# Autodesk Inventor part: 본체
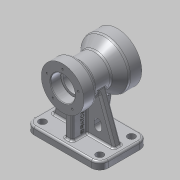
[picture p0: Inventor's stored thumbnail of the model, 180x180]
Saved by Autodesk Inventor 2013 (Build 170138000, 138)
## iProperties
Created: 2015-08
Part Number: 본체
Material: 알루미늄 6061
Document SubType Name: Modeling
Designer: ST1
Density: 2.71 g/cm^3
Mass: 1063.17 g
Surface Area: 754.745 cm^2
Volume: 392.315 cm^3
Author: ST1
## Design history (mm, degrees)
sketch "스케치1"
  geometry: L1 (-61, 40)-(61, 40); L2 (61, 40)-(61, -40); L3 (61, -40)-(-61, -40); L4 (-61, -40)-(-61, 40); 1 further point
  constraints: 8 end point, 2 parallel, 1 horizontal, 1 perpendicular
  dimensions: "d0" = 122 distance of L1.start L1.end; "d2" = 80 distance of L3.end L1.start; "d3" = 40 distance from line of point (0, 0) L1; "d4" = 61 distance from line of point (0, 0) L4
extrude "돌출1" new body sketch "스케치1" distance "d5" = 12; taper "d6" = 0 deg
sketch "스케치2"
  geometry: L1 (-40, 90)-(42.312, 90); L2 (-40, 110)-(-40, 125); L3 (-40, 125)-(-20, 125); L4 (-20, 125)-(-14.804, 116); L5 (-14.804, 116)-(13.315, 116); L6 (13.315, 116)-(30, 130); L7 (30, 130)-(50, 130); L8 (50, 130)-(50, 116); L9 (50, 116)-(30, 116); L10 (-40, 0)-(-40, 12) reference; L11 (30, 116)-(30, 109); L12 (30, 109)-(27, 109); L13 (27, 109)-(27, 106); L14 (27, 106)-(-23, 106); L15 (-23, 106)-(-23, 110); L16 (-23, 110)-(-40, 110); 1 further point
  constraints: 30 end point, 7 perpendicular, 5 parallel, 1 horizontal
  dimensions: "d7" = 90 distance from line of point (0, 0) L1; "d12" = 20 distance from line of L3.end L2; "d13" = 0 distance from line of L10 L1.start; "d14" = 0 distance from line of L1.start L2; "d15" = 90 distance between parallel lines of L8 L2; "d16" = 20 distance from line of L6.end L8; "d18" = 60 deg angle of L4 L5; "d60" = 80 diameter of L7 L1; "d61" = 70 diameter of L3 L1; "d62" = 52 diameter of L9 L1; "d63" = 38 diameter of L12 L1; "d65" = 32 diameter of L14 L1; "d66" = 40 diameter of L16 L1; "d67" = 17 distance between parallel lines of L15 L2; "d68" = 52 diameter of L5 L1; "d69" = 20 distance between parallel lines of L11 L8; "d70" = 3 distance between parallel lines of L13 L11; "d126" = 40 deg angle of L6 L5
revolve "회전1" sketch "스케치2" stored, may be unused: angle "d26" = 90 deg
sketch "스케치3"
  geometry: L1 (-61, 12)-(61, 12) reference; L2 (25.091, 83.185)-(51, 12); L3 (61, 0)-(61, 12) reference; L4 (-25.091, 83.185)-(-51, 12); L5 (-61, 0)-(-61, 12) reference; L6 (-51, 12)-(51, 12); C1 r 26 at (0, 90) reference; A1 r 26 centre (0, 90) between (-25.091, 83.185) and (25.091, 83.185); 1 further point
  constraints: 6 end point, 2 point on circle, 2 point on line, 1 centre point, 1 coincident, 1 collinear
  dimensions: "d27" = 10 distance from line of L3 L2.end; "d28" = 70 deg angle of L2 L1; "d29" = 10 distance from line of L5 L4.end; "d30" = 70 deg angle of L1 L4; "d33" = 52 diameter of A1
extrude "돌출2" join sketch "스케치3" stored distance "d34" = 12; taper "d35" = 0 deg
sketch "스케치4"
  geometry: L1 (50, 50)-(50, 130) reference; L2 (30, 50)-(30, 130) reference; 1 further point
extrude "돌출3" join sketch "스케치4" stored distance "d39" = 12; taper "d40" = 0 deg
sketch "스케치5"
  geometry: L1 (0, 64)-(6, 64) reference; L2 (18, 36)-(18, 30); L3 (30, 30)-(30, 36); L4 (-61, 0)-(61, 0) reference; A1 r 6 centre (24, 30) between (18, 30) and (30, 30); A2 r 6 centre (24, 36) between (30, 36) and (18, 36); 1 further point
  constraints: 4 end point, 4 point on circle, 4 tangent, 2 centre point, 1 parallel, 1 perpendicular
  dimensions: "d41" = 18 dimension on A1 A2; "d43" = 12 distance between parallel lines of L3 L2; "d44" = 30 distance from line of L4 A1.centre; "d45" = 24 horizontal distance of point (0, 0) A1.centre
extrude "돌출4" cut sketch "스케치5" distance "d46" = 12; taper "d47" = 0 deg
fillet "모깎기1" dims "d48" = 14
fillet "모깎기2" dims "d49" = 3
sketch "스케치6"
  geometry: C1 r 6 at (47, 26); A1 r 11 centre (47, 26) between (58, 26) and (47, 37) reference; 1 further point
  constraints: 1 centre point, 1 coincident
  dimensions: "d50" = 12 diameter of C1
extrude "돌출5" cut sketch "스케치6" distance "d52" = 12; taper "d53" = 0 deg
sketch "스케치7" dims "d71" = 54
  geometry: C1 r 35 at (0, 0) reference; C2 r 20 at (0, 0) reference; 3 further points
  constraints: 1 coincident, 1 vertical alignment, 2 other
  dimensions: "d73" = 0 horizontal distance of C1.centre point (0, 27)
hole "구멍1" sketch "스케치7" at (0, 27) diameter "d74" = 3.242; stored, may be unused: countersink angle "d78" = 90 deg, drill point angle "d80" = 118 deg; dims "d75" = 10, "d76" = 4, "d77" = 2, "d79" = 13
sketch "스케치8" dims "d84" = 66
  geometry: C1 r 26 at (0, 0) reference; C2 r 40 at (0, 0) reference; 3 further points
  constraints: 1 coincident, 1 vertical alignment, 2 other
  dimensions: "d86" = 0 horizontal distance of point (0, -33) C1.centre
hole "구멍2" sketch "스케치8" at (0, -33) diameter "d87" = 3.242; stored, may be unused: countersink angle "d91" = 90 deg, drill point angle "d93" = 118 deg; dims "d88" = 10, "d89" = 4, "d90" = 2, "d92" = 13
sketch "스케치9"
  geometry: L1 (-40, 55)-(-20, 55) reference; L2 (-20, 55)-(-14.804, 64) reference; L3 (-14.804, 64)-(13.315, 64) reference; L4 (13.315, 64)-(30, 50) reference; L5 (30, 50)-(50, 50) reference; L6 (26, 12)-(37, 12) reference; L7 (20, 12)-(32, 12) reference; L8 (-26, 12)-(26, 12) reference; L9 (-32, 12)-(-20, 12) reference; L10 (-37, 12)-(-26, 12) reference; L11 (-30, 55)-(-30, 12); L12 (-40, 0)-(-40, 9) reference; L13 (36.7, 50)-(30, 12); L14 (40, 9)-(40, 0) reference; 1 further point
  constraints: 4 end point, 3 point on line, 1 midpoint, 1 perpendicular
  dimensions: "d101" = 10 distance between parallel lines of L12 L11; "d102" = 80 deg angle of L6 L13; "d103" = 10 distance from line of L14 L13.end
feature "리브1" sketch "스케치9" dims "d104" = 1, "d105" = 12, "d106" = 0, "d107" = 0, "d108" = 1, "d109" = 1
sketch "스케치10"
  geometry: L1 (30, 50)-(50, 50) reference; L2 (-26, 12)-(26, 12) reference; L3 (20, 12)-(32, 12) reference; L4 (26, 12)-(37, 12) reference; L5 (36.7, 50)-(30, 12); L6 (40, 9)-(40, 0) reference; 1 further point
  constraints: 2 end point, 2 point on line
  dimensions: "d110" = 80 deg angle of L4 L5; "d111" = 10 distance from line of L6 L5.end
feature "리브2" sketch "스케치10" dims "d112" = 1, "d113" = 12, "d114" = 0, "d115" = 0, "d116" = 1, "d117" = 1
fillet "모깎기3" dims "d118" = 3
fillet "모깎기4" dims "d119" = 3
fillet "모깎기5" dims "d120" = 3
fillet "모깎기6" dims "d121" = 3
fillet "모깎기7" dims "d122" = 3
fillet "모깎기8" dims "d123" = 3
fillet "모깎기9" dims "d124" = 0.3
sketch "스케치11"
  geometry: L1 (-12.261, 9.998)-(-29.739, 9.998); L2 (-29.739, 9.998)-(-29.739, 16.002); L3 (-29.739, 16.002)-(-12.261, 16.002); L4 (-12.261, 16.002)-(-12.261, 9.998); L5 (-29.739, 13)-(-12.261, 13); L6 (-21, 9.998)-(-21, 16.002); L7 (15, 53)-(15, 1) reference; L8 (-37.119, -3)-(0, -3) reference; L9 (3, -10)-(3, 1) reference; 1 further point
  constraints: 4 end point, 4 midpoint, 2 other
  dimensions: "d128" = 16 distance between parallel lines of L8 L5; "d129" = 24 distance between parallel lines of L9 L6
extrude "돌출6" join sketch "스케치11" distance "d130" = 0.5; taper "d131" = 0 deg
chamfer "모따기1" distance "d132" = 1; stored, may be unused: second distance "d133" = 2, angle "d134" = 45 deg
fillet "모깎기10" dims "d135" = 5
fillet "모깎기11" dims "d136" = 3
node "솔리드1"
mirror "대칭1"
pattern_linear "직사각형 패턴1" dims "d56" = 94, "d59" = 52
pattern_circular "원형 패턴1" dims angle "d82" = 360 deg
pattern_circular "원형 패턴2" dims angle "d95" = 360 deg
node "투영된 루프1"
